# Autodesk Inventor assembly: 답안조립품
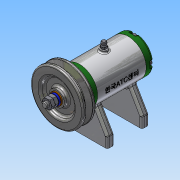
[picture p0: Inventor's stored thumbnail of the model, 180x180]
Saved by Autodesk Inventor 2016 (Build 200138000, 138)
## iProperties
Created: 2018-05
Part Number: 답안조립품
Material: 일반
Document SubType Name: Assembly
Designer: Administrator
Author: Administrator
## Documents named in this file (16)
- C:\Users\Administrator\Desktop\480507V1017\답안조립품.iam
- C:\Users\Administrator\Desktop\480507V1017\본체.ipt
- C:\Users\Administrator\Desktop\480507V1017\축.ipt
- C:\Users\Administrator\Desktop\480507V1017\베어링 6002.ipt
- C:\Users\Administrator\Desktop\480507V1017\뒤커버.ipt
- C:\Users\Administrator\Desktop\480507V1017\앞커버.ipt
- C:\Users\Administrator\Desktop\480507V1017\볼트 M4x12.ipt
- C:\Users\Administrator\Desktop\480507V1017\오일 실 15 25 7.ipt
- C:\Users\Administrator\Desktop\480507V1017\V벨트풀리.ipt
- C:\Users\Administrator\Desktop\480507V1017\키 3x3x12.ipt
- C:\Users\Administrator\Desktop\480507V1017\와셔 8x17.ipt
- C:\Users\Administrator\Desktop\480507V1017\스프링와셔 8.ipt
- C:\Users\Administrator\Desktop\480507V1017\너트 M8.ipt
- C:\Users\Administrator\Desktop\480507V1017\니플 M6x0.75.ipt
- C:\Users\Administrator\Desktop\480507V1017\와셔 6x11.5.ipt
- C:\Users\Administrator\Desktop\480507V1017\볼트 M6x8.ipt
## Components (1 placed, 1 different names)
1. V벨트풀리:1
